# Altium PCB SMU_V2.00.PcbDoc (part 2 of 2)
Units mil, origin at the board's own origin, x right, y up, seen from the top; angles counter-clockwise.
Board outline 8661.42 x 7437.01 mil, 4 copper layers (Component Side, Ground Plane, Power Plane, Solder Side), stack 33.234 mil thick; 223 components, 143 nets, 756 pads, 732 vias.
Unrouted connection lines stored in the file: 6.
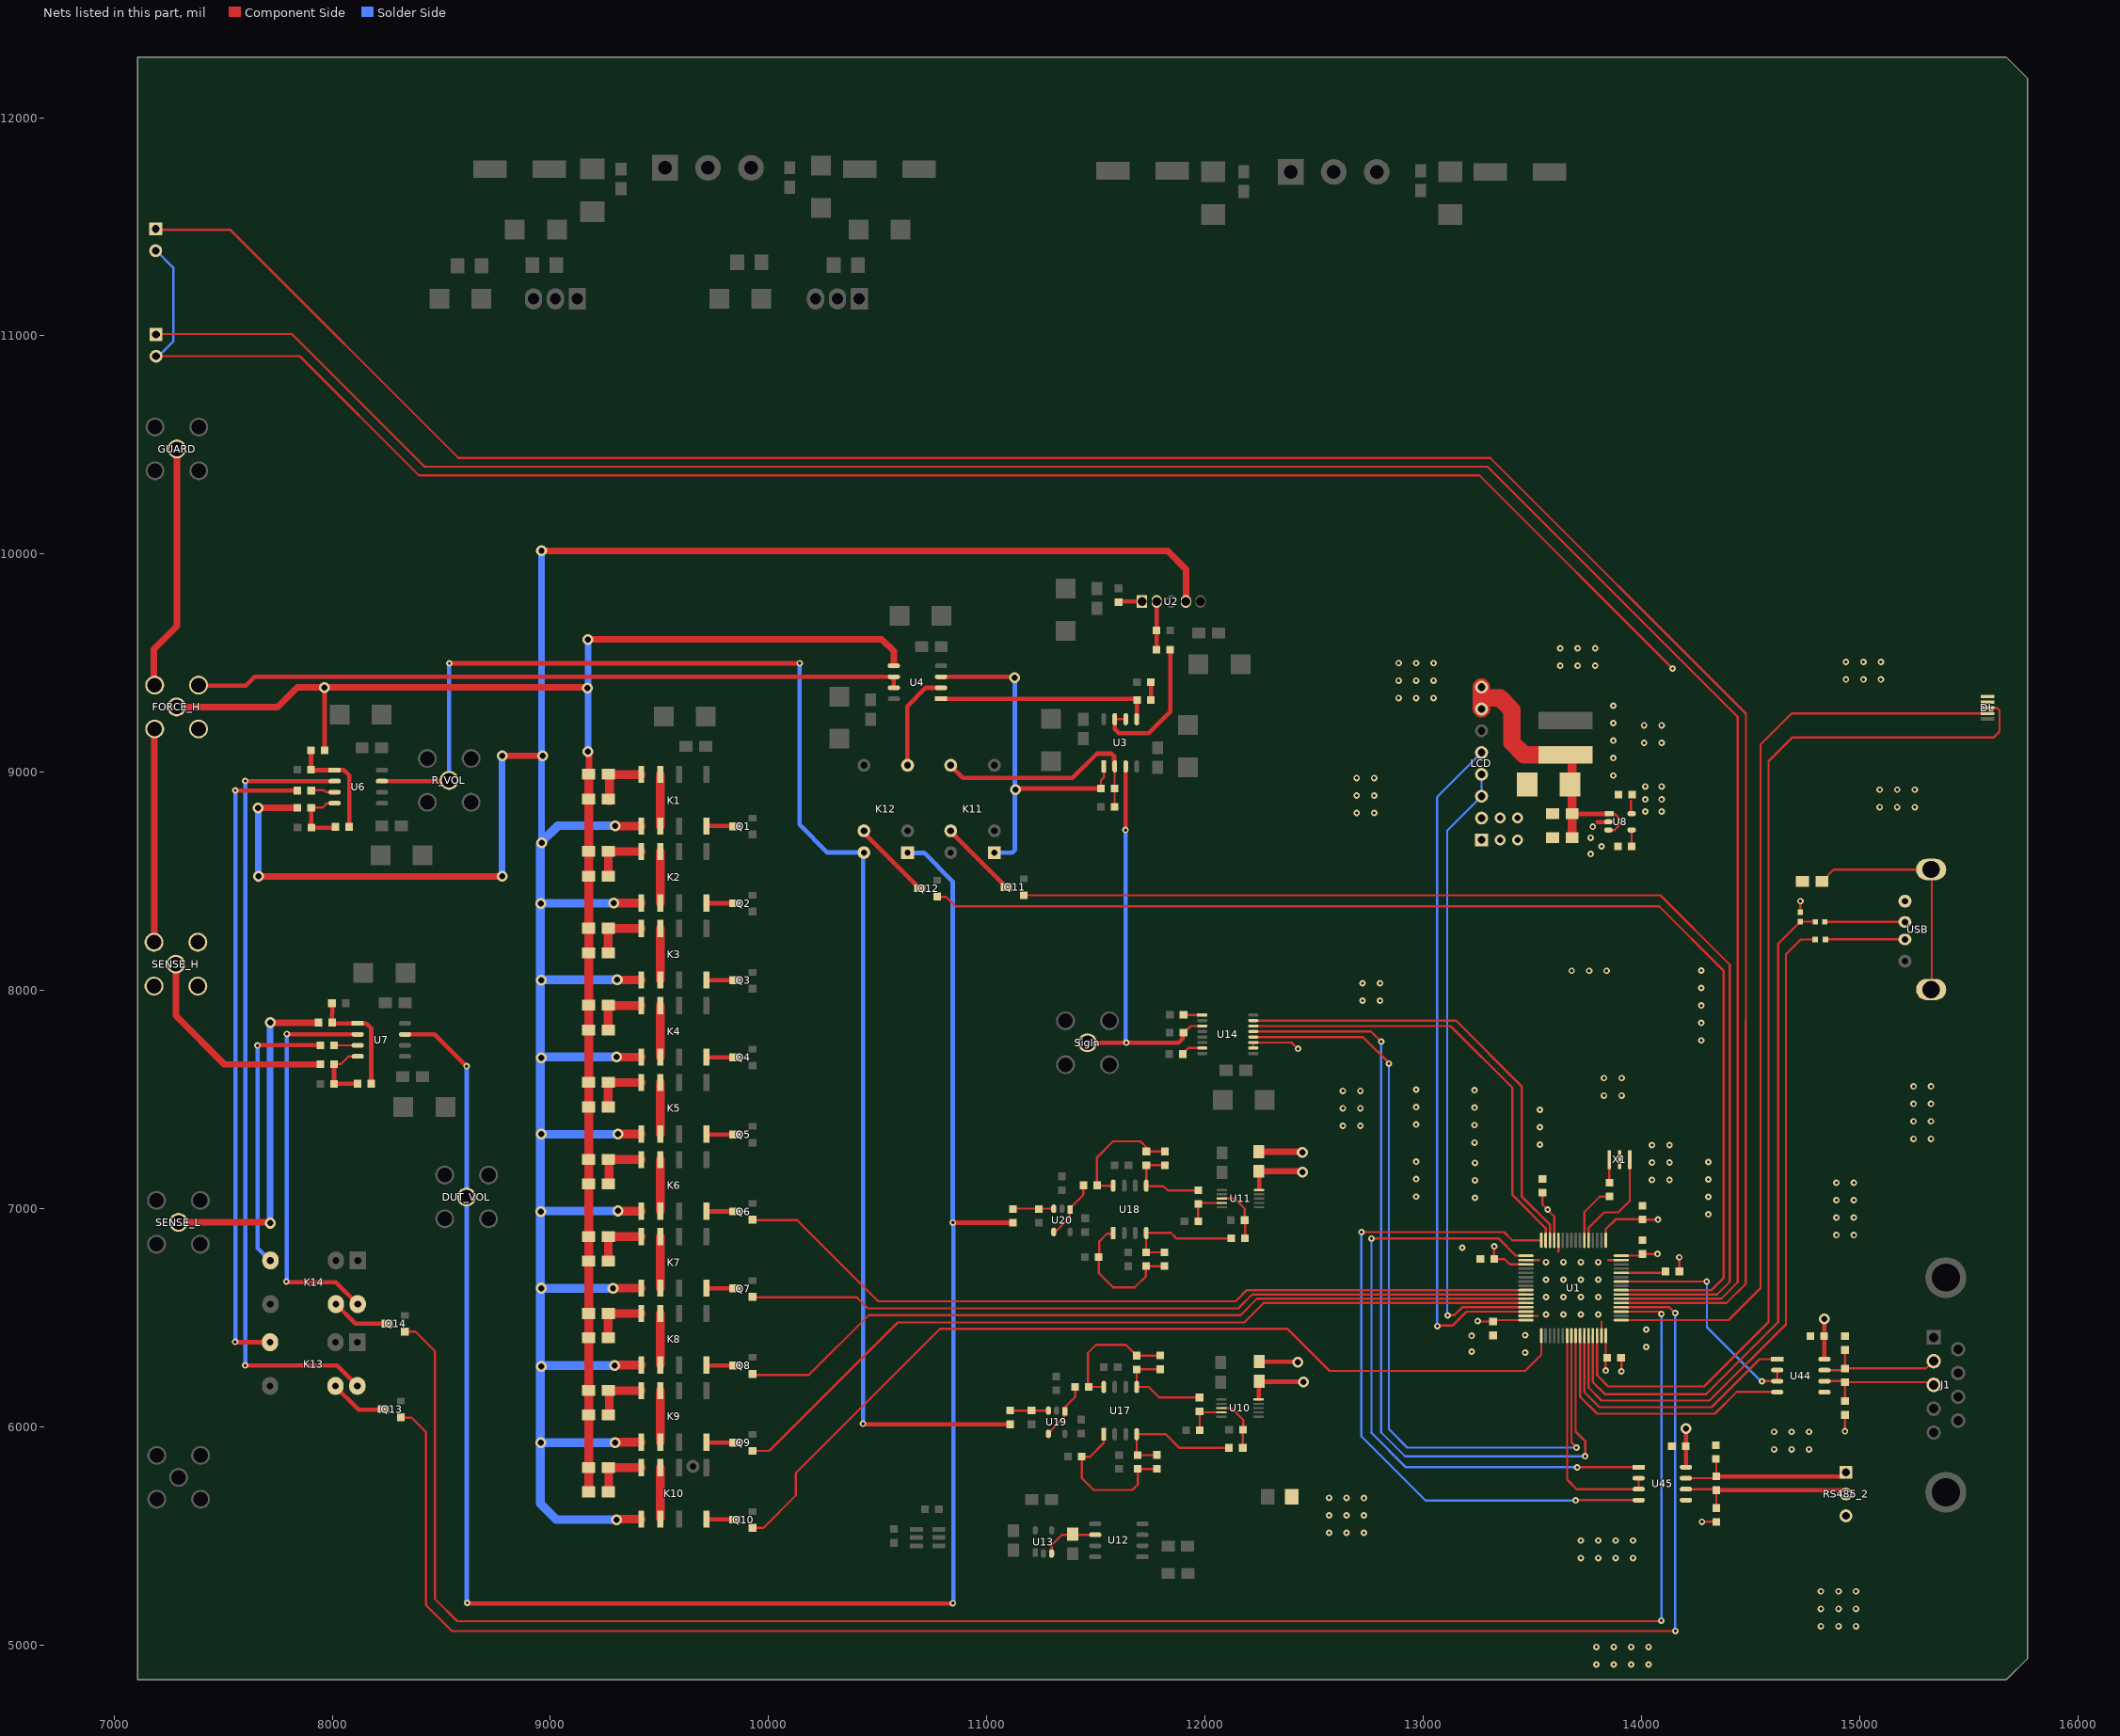
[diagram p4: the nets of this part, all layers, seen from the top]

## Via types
v1: diameter 30/30 (per signal layer), hole 14, Component Side to Solder Side, 595 vias
v2: diameter 50, hole 28, Component Side to Solder Side, 98 vias
v3: diameter 30, hole 14, Component Side to Solder Side, 35 vias
v4: diameter 39.37, hole 29.53, Component Side to Solder Side, 2 vias
v5: diameter 66.93, hole 47.24, Component Side to Solder Side, 2 vias

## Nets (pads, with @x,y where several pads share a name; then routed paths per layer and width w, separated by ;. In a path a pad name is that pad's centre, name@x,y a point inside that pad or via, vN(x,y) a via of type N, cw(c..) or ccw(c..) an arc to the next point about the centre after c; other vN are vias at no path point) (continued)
CTRL6: Q6.1 U1.25 | length 3727.3
  Component Side w10: Q6.1@9917.83,6946.89 10130.76,6946.89 10501.98,6575.67 12140.06,6575.67 12191.29,6626.9 U1.25@13470.11,6626.9
CTRL7: Q7.1 U1.26 | length 3593.2
  Component Side w10: Q7.1@9924.31,6593.69 10404.25,6593.69 10454.72,6543.22 12151.86,6543.22 12211.24,6602.6 12212.32,6602.6 12216.93,6607.22 U1.26@13470.11,6607.22
CTRL8: Q8.1 U1.27 | length 3691.7
  Component Side w10: Q8.1@9922.68,6238.83 10184.86,6238.83 10459.05,6512.43 12162.72,6512.43 12237.82,6587.53 U1.27@13470.11,6587.53
CTRL9: Q9.1 U1.28 | length 3828.3
  Component Side w10: Q9.1@9922.68,5889.82 10002.84,5889.82 10591.34,6478.32 12178.79,6478.32 12268.32,6567.85 U1.28@13470.11,6567.85
CTRL10: Q10.1 U1.33 | length 4271.5
  Component Side w10: Q10.1@9920.57,5537.65 9976.4,5537.65 10124.87,5686.12 10124.87,5788.27 10786.64,6450.03 12376.69,6450.03 12570.4,6256.32 13466.42,6256.32 13540.97,6330.87 U1.33@13540.97,6418.24 ; Q10.1@9922.12,5537.11 Q10.1@9922.12,5551.99
CTRL11: Q11.1 U1.55 | length 5343.6
  Component Side w10: Q11.1@11166.58,8436.12 14086.59,8436.12 14404.05,8118.66 14404.05,6664.84 14346.42,6607.22 U1.55@13907.11,6607.22
CTRL12: Q12.1 U1.56 | length 5650
  Component Side w10: Q12.1@10766.33,8428.85 10813.29,8428.85 10856.41,8385.73 14080.95,8385.74 14375.68,8091.01 14375.68,6681.39 14321.19,6626.9 U1.56@13907.11,6626.9
CTRL13: Q13.1 U1.52 | length 8423.7
  Component Side w10: Q13.1@8316.05,6042.29 8363.72,6042.29 8429.56,5976.45 8429.56,5182.38 8548.04,5063.9 v3@14154.58,5063.9 ; U1.52@13907.11,6548.16 14128.51,6548.16 v3@14154.38,6522.29
  Solder Side w10: v3@14154.38,5064.46 v3(14154.38,6521.19)
  other v3: 14155.22,5065.06
CTRL14: Q14.1 U1.51 | length 8575.1
  Component Side w10: Q14.1@8326.42,6436.35 8381.6,6436.35 8470.69,6347.26 8470.69,5212.23 8573.14,5109.78 v3@14092.23,5109.78 ; U1.51@13907.11,6528.48 14079.18,6528.48 v3@14089.4,6518.25
  Solder Side w10: v3@14091.54,5108.76 v3(14091.54,6517.14)
  other v3: 14090.77,5112.36
D1: K1.8 Q1.3 | length 133.6
  Component Side w20: K1.8@9715.55,8753.74 Q1.3@9849.19,8753.74
D2: K2.8 Q2.3 | length 130.3
  Component Side w20: K2.8@9715.03,8399.71 Q2.3@9845.34,8399.71
D3: K3.8 Q3.3 | length 130.4
  Component Side w20: K3.8@9714.93,8046.63 Q3.3@9845.34,8046.63
D3V3: C1.2 C2.2 C3.2 C4.2 C5.2 C6.2 C22.2 C29.2 C81.2 C85.2 C108.2 LED0.2 LED1.2 R42.1 R102.2 R105.2 U1.1 U1.13 U1.19 U1.32 U1.48 U1.64 U8.5 U10.10 U11.10 U14.10 U14.11 U44.8 U45.8 | length 10898.9
  Component Side w10: LED1.2@7176.54,10907.22 7850.27,10907.22 8397.18,10360.31 13256.88,10360.31 v1(14141.88,9475.31) ; U14.10@12221.05,7736.31 U14.11@12221.05,7758.94 ; U14.11@12226.3,7761.51 12395.95,7761.51 12424.84,7732.62 v1@12426.19,7732.62 ; C81.2@12245.46,6205.52 C81.2@12245.63,6205.52 ; v1@13245.25,6482.49 C6.2@13319.59,6482.49 ; C2.2@13312.76,6768.97 13372.99,6768.97 13396.94,6745.01 U1.19@13470.11,6745.01 ; C6.2@13319.59,6489.11 U1.32@13470.11,6489.11 ; C2.2@13324.77,6770.14 v1@13324.77,6828.08 ; C1.2@13546.28,7074.6 13546.28,7018.74 13600.03,6964.99 U1.13@13600.03,6855.25 ; v1(13835.74,6258.05) C5.2@13835.74,6314.15 ; C5.2@13836.25,6305.29 U1.48@13836.25,6418.24 ; U1.1@13836.25,6855.25 13836.25,6906.38 13881.15,6951.29 C4.2@14009.16,6951.29 ; U1.64@13907.11,6784.38 C3.2@14009.72,6784.38 ; U8.5@13950.9,8809.48 13950.9,8869.84 ; C4.2@14003.81,6950.29 v1@14078.83,6950.29 ; C3.2@14004.91,6792.07 v1@14075.54,6792.07 ; v1(14277.12,5565.07) R105.2@14342.63,5565.07 ; R42.1@14727.91,8358.3 v1(14727.91,8409.28) ; v2(14838.42,6495.31) v2@14838.42,6508.77 ; v1(14932.63,5979.56) R102.2@14932.63,6055.07
  Component Side w20: C81.2@12237.78,6207.05 v2@12452.91,6207.05 ; U10.10@12245.63,6128.67 C81.2@12245.63,6205.52 ; U11.10@12248.04,7089.45 C85.2@12248.04,7167.65 ; U45.8@14203.42,5815.31 v2(14203.42,5991.84) ; U44.8@14838.42,6310.31 v2(14838.42,6495.31)
  Component Side w30: C85.2@12245.91,7171.67 v2@12446.62,7171.67
  Solder Side w10: LED1.2@7192.45,10906.75 7203.88,10906.75 7271.25,10974.11 7271.25,11313 LED0.2@7193.23,11391.03
  other v1: 13248.99,6485.31 14072.89,6792.52 13325.59,6826.87 14075.08,6949.95 13569.87,6996 12426.15,7732.55 14016.88,8820.31 14091.88,8820.31 14016.88,8875.31 14091.88,8875.31 14016.88,8935.31 14091.88,8935.31
  other v2: 12450.69,6206.47 12446.59,7168.16
D4: K4.8 Q4.3 | length 133.8
  Component Side w20: K4.8@9711.55,7693.54 Q4.3@9845.34,7693.54
D5: K5.8 Q5.3 | length 132.6
  Component Side w20: K5.8@9712.77,7340.46 Q5.3@9845.34,7340.46
D5V0: C57.2 C58.2 C59.1 L2.2 LCD.7 LCD.8 U8.1 U8.3 | length 1367.8
  Component Side w10: U8.3@13844.6,8734.68 13876.25,8734.68 13896.88,8755.31 13896.88,8790.31 13877.71,8809.48 U8.1@13844.6,8809.48
  Component Side w22: C58.2@13682.71,8809.48 U8.1@13844.6,8809.48
  Component Side w40: C57.2@13682.34,8700.76 13682.34,8935.31 L2.2@13682.34,9070.07
  Component Side w80: LCD.7@13266.88,9290.31 LCD.8@13266.88,9390.31 ; 13266.88,9340.31 13351.88,9340.31 13406.88,9285.31 13406.88,9135.31 13461.88,9080.31 L2.2@13651.88,9080.31
D6: K6.8 Q6.3 | length 126.8
  Component Side w20: K6.8@9718.57,6987.37 Q6.3@9845.34,6987.37
D7: K7.8 Q7.3 | length 128.9
  Component Side w20: K7.8@9716.44,6634.29 Q7.3@9845.34,6634.29
D8: K8.8 Q8.3 | length 127
  Component Side w20: K8.8@9718.38,6281.21 Q8.3@9845.34,6281.21
D9: K9.8 Q9.3 | length 132
  Component Side w20: K9.8@9713.35,5928.12 Q9.3@9845.34,5928.12
D10: K10.8 Q10.3 | length 128
  Component Side w20: K10.8@9715.55,5576.99 Q10.3@9843.53,5576.99
D11: K11.5 Q11.3 | length 359.8
  Component Side w10: K11.5@10834.46,8728.35 K11.5@10834.46,8732.05
  Component Side w20: K11.5@10834.46,8728.35 Q11.3@11086.28,8476.53
D12: K12.5 Q12.3 | length 371.1
  Component Side w10: K12.5@10436.55,8722.75 K12.5@10436.55,8732.05
  Component Side w20: K12.5@10436.55,8722.75 Q12.3@10692.41,8466.89
D13: K13.5 Q13.3 | length 267.4
  Component Side w10: K13.5@8014.82,6185.08 K13.5@8014.82,6187.86
  Component Side w20: K13.5@8014.82,6185.08 8120.68,6079.23 Q13.3@8235.57,6079.23
D14: K14.5 Q14.3 | length 284.6
  Component Side w20: K14.5@8016.68,6562.69 8106.59,6472.77 Q14.3@8264.05,6472.77
DAC1_FSYNC: U1.41 U14.13 | length 3942.5
  Component Side w10: U14.13@12222.43,7811.9 12760.69,7811.9 ; 12762.48,7809.72 v1(12806.88,7765.31) ; U1.41@13698.45,6418.24 13698.45,5978.74 13741.88,5935.31 v1(13741.88,5865.31)
  Solder Side w10: v1(12806.88,7765.31) 12806.88,5975.31 12916.88,5865.31 v1(13741.88,5865.31)
DAC1_RESET: U1.14 U14.15 | length 2110.4
  Component Side w10: U14.15@12224.6,7862.29 13149.46,7862.29 13450.72,7561.03 13450.72,7056.85 13580.34,6927.22 U1.14@13580.34,6855.25
DAC1_SCLK: U1.40 U14.12 | length 3762.8
  Component Side w10: U14.12@12224.06,7786.7 12723.86,7786.7 12841.88,7668.68 v1(12841.88,7665.31) ; U1.40@13678.77,6418.24 13678.77,5928.43 v1(13701.88,5905.31)
  Solder Side w10: v1(12841.88,7665.31) 12841.88,5990.31 12926.88,5905.31 v1(13701.88,5905.31)
DAC1_SDATA: U1.15 U14.14 | length 2059.5
  Component Side w10: U14.14@12225.14,7837.1 13125.18,7837.1 ; 13127.08,7835.11 13408.8,7553.4 13408.8,7062.49 13560.66,6910.63 U1.15@13560.66,6855.25
DGND: C1.1 C2.1 C3.1 C4.1 C5.1 C6.1 C22.1 C23.1 C29.1 C57.1 C58.1 C59.2 C81.1 C85.1 C108.1 DL.5 L1.2 L3.2 LCD.1 LCD.2 R2.2 R101.2 R104.2 RS485_2.3 U1.12 U1.18 U1.31 U1.47 U1.63 U8.2 U44.5 U45.5 USB.4 X1.2 | length 843.6
  Component Side w10: U1.31@13470.11,6508.79 13525.37,6508.79 ; U1.18@13470.11,6764.7 13531.27,6764.7 ; 13619.71,6802.48 U1.12@13619.71,6855.25 ; U1.47@13816.56,6418.24 13816.56,6481.79 ; 13847.49,6764.7 U1.63@13907.11,6764.7 ; v1(13907.96,6253.87) C5.1@13907.96,6317.13 ; R2.2@14173.57,6712.43 v1@14173.57,6775.64
  Component Side w20: C81.1@12249.04,6299.06 v2@12422.09,6299.06 ; 13798.66,8772.08 U8.2@13844.6,8772.08
  Component Side w30: C85.1@12245.91,7261.67 v2@12451.64,7261.67
  other v1: 13792.56,4911.52 13872.56,4911.52 13952.56,4911.52 14032.56,4911.52 13792.56,4991.52 13872.56,4991.52 13952.56,4991.52 14032.56,4991.52 14822.53,5086.38 14902.53,5086.38 14982.53,5086.38 14822.53,5166.38 14902.53,5166.38 14982.53,5166.38 14822.53,5246.38 14902.53,5246.38 14982.53,5246.38 13721.63,5399.14 13801.63,5399.14 13881.63,5399.14 13961.63,5399.14 13721.63,5479.14 13801.63,5479.14 13881.63,5479.14 13961.63,5479.14 12568.37,5515.09 12648.37,5515.09 12728.37,5515.09 12568.37,5595.09 12648.37,5595.09 12728.37,5595.09 12728.25,5673.54 12568.37,5675.09 12648.37,5675.09 14607.34,5897.3 14687.34,5897.3 14767.34,5897.3 14607.34,5977.3 14687.34,5977.3 14767.34,5977.3 13466.88,6340.31 13221.75,6344.34 14021.33,6366.39 13220.96,6417.42 13466.88,6420.31 14021.33,6446.39 13561.88,6515.31 13641.88,6515.31 13721.88,6515.31 13801.88,6515.31 13561.88,6595.31 13641.88,6595.31 13721.88,6595.31 13801.88,6595.31 13561.88,6675.31 13641.88,6675.31 13721.88,6675.31 13801.88,6675.31 13561.88,6755.31 13641.88,6755.31 13721.88,6755.31 13801.88,6755.31 14173.16,6777.15 13178.69,6821.71 14893.33,6879.01 14973.33,6879.01 14893.33,6959.01 14973.33,6959.01 14306.08,6973.73 14893.33,7039.01 14973.33,7039.01 13236.88,7050.31 14306.08,7053.73 12966.88,7055.31 14893.33,7119.01 14973.33,7119.01 13236.88,7130.31 14048.35,7131.47 14128.35,7131.47 14306.08,7133.73 12966.88,7135.31 13236.88,7210.31 14048.35,7211.47 14128.35,7211.47 14306.08,7213.73 12966.88,7215.31 14048.35,7291.47 14128.35,7291.47 13534.13,7293.67 13234.52,7303.01 15246.88,7320.31 15326.88,7320.31 13534.13,7373.67 12631.88,7380.31 12711.88,7380.31 13234.52,7383.01 12966.88,7385.31 15246.88,7400.31 15326.88,7400.31 13534.13,7453.67 12631.88,7460.31 12711.88,7460.31 13234.52,7463.01 12966.88,7465.31 15246.88,7480.31 15326.88,7480.31 13828.57,7518.66 13908.57,7518.66 12631.88,7540.31 12711.88,7540.31 13234.52,7543.01 12966.88,7545.31 15246.88,7560.31 15326.88,7560.31 13828.57,7598.66 13908.57,7598.66 14273.54,7771.1 14273.54,7851.1 14273.54,7931.1 12721.88,7953.43 12801.88,7953.43 14273.54,8011.1 12721.88,8033.43 12801.88,8033.43 13679.84,8090.23 13759.84,8090.23 13839.84,8090.23 14273.54,8091.1 13766.88,8625.31 13816.88,8660.31 13766.88,8700.31 13776.88,8750.31 12694.62,8813.79 12774.62,8813.79 15091.88,8840.31 15171.88,8840.31 15251.88,8840.31 12694.62,8893.79 12774.62,8893.79 15091.88,8920.31 15171.88,8920.31 15251.88,8920.31 12694.62,8973.79 12774.62,8973.79 13870.46,8985.13 13870.46,9065.13 14011.88,9135.31 14091.88,9135.31 13870.46,9145.13 14011.88,9215.31 14091.88,9215.31 13870.46,9225.13 13870.46,9305.13 12886.88,9340.31 12966.88,9340.31 13046.88,9340.31 12886.88,9420.31 12966.88,9420.31 13046.88,9420.31 14936.88,9425.31 15016.88,9425.31 15096.88,9425.31 13627.78,9488.72 13707.78,9488.72 13787.78,9488.72 12886.88,9500.31 12966.88,9500.31 13046.88,9500.31 14936.88,9505.31 15016.88,9505.31 15096.88,9505.31 13627.78,9568.72 13707.78,9568.72 13787.78,9568.72
  other v2: 12425.75,6296.93 12445.7,7258.73 13351.88,8690.31 13431.88,8690.31 13351.88,8790.31 13431.88,8790.31
DUT_VOLTAGE: DUT_VOL.1 K12.1 R51.2 U7.7 | length 8897.1
  Component Side w20: U7.7@8333.23,7798.88 8468.01,7798.88 v3@8613.08,7653.82 ; v3@8614.43,5190.9 v3@10847.87,5190.9 ; v3@10841.24,6935.57 R51.2@11119.82,6935.57
  Solder Side w20: v3@8616.34,5192.67 v3@8616.34,7656.93 ; K12.1@10633.99,8630.67 10712.84,8630.67 10843.28,8500.23 v3@10843.28,6935.17 ; v3@10845.98,5191.13 v3@10845.98,6943.61
  other v3: 10844.16,5191.95 8618.51,5193.22 10844.41,6936.49 8615.4,7652.69
FB_R_T1: C70.1 C71.1 C72.1 C73.1 C74.1 C75.1 C76.1 C77.1 C78.1 C79.1 FORCE_H.1 R19.2 R31.1 R32.1 R33.1 R34.1 R35.1 R36.1 R37.1 R38.1 R39.1 R40.1 U4.5 | length 7622.6
  Component Side w10: v2(7963.23,9388.71) v2@7965.15,9388.71
  Component Side w20: R19.2@7965.15,9100.94 v2@7965.15,9388.71
  Component Side w30: FORCE_H.1@7284.41,9298.47 7748.92,9298.47 7839.16,9388.71 v2(7963.23,9388.71) ; v2@7965.15,9388.71 v2@9170.85,9388.71 ; v2@9165.48,9609.56 10518.48,9609.56 10573.43,9554.61 U4.5@10573.43,9491.17 ; R31.1@9171.24,8985.77 9176.58,8991.11 v2@9176.58,9099.16
  Component Side w40: C79.1@9175.42,5705.38 R40.1@9175.42,5813.12 C78.1@9175.42,6055.22 R39.1@9175.42,6166.28 C77.1@9175.42,6407.94 R38.1@9175.42,6519.44 C76.1@9175.42,6760.67 R37.1@9175.42,6872.6 C75.1@9175.42,7113.4 R36.1@9175.42,7225.76 C74.1@9175.42,7466.13 R35.1@9175.42,7578.92 C73.1@9175.42,7818.86 R34.1@9175.42,7932.09 C72.1@9175.42,8171.58 R33.1@9175.42,8285.25 C71.1@9175.42,8524.31 R32.1@9175.42,8638.41 C70.1@9175.42,8877.04 R31.1@9175.42,8991.57
  Solder Side w30: v2(9171.77,9095) v2@9171.77,9610.04
  other v2: 9169.88,9386.28 9171.77,9608.65
FB_R_T2: K1.5 K2.5 K3.5 K4.5 K5.5 K6.5 K7.5 K8.5 K9.5 K10.5 R21.2 U2.4 | length 14501
  Component Side w30: v2@7654.09,8837.22 R21.2@7840.73,8837.22 ; v2(7662.06,8523.46) v2@8776.36,8523.46 ; v2(8779.53,9075.6) v2@8961.35,9075.6 ; v2@8955.66,10013.74 11828.42,10013.74 11911.99,9930.18 U2.4@11911.99,9782.7
  Component Side w40: v2@9287.6,6635.91 K7.5@9416.34,6635.91 ; v2@9288.99,8400.76 K2.5@9416.34,8400.76 ; v2@9289.28,6282.93 K8.5@9416.34,6282.93 ; v2@9296.82,5929.96 K9.5@9416.34,5929.96 ; v2@9297.25,7694.82 K4.5@9416.34,7694.82 ; v2@9298.95,8753.74 K1.5@9416.34,8753.74 ; v2@9304.27,5576.99 K10.5@9416.34,5576.99 ; v2@9307.92,8047.79 K3.5@9416.34,8047.79 ; v2@9309.83,6988.88 K6.5@9416.34,6988.88 ; v2@9314.01,7341.85 K5.5@9416.34,7341.85
  Solder Side w10: v2@8952.92,6989.61 v2@8953.9,6989.61 ; v2(8959.34,8676.88) v2@8959.34,8680.45
  Solder Side w30: v2@7660.42,8511.83 v2(7660.42,8836.35) ; v2(8778.29,8524.51) v2@8778.29,9063.78 ; v2@8959.34,8680.45 v2@8959.34,10012.66
  Solder Side w40: v2@8956.15,6281.23 v2(9293.52,6281.23) ; v2@8957.46,6634.94 v2(9286.79,6634.94) ; v2@8960.46,7695.1 v2(9303.13,7695.1) ; v2@8960.49,8399.92 v2(9289.6,8399.92) ; v2@8962.72,8049.77 v2(9306.02,8049.77) ; v2@8963.99,7341.39 v2(9308.9,7341.39) ; v2(9296.41,5927.52) v2@8953.9,5927.52 ; v2@9300.6,8755.61 9034.5,8755.61 8959.34,8680.45 8953.9,8675.01 v2@8953.9,6989.61 ; v2(9303.13,5574.77) 9027.3,5574.77 8953.9,5648.16 v2@8953.9,5927.52 ; v2(9308.9,6989.61) v2@8953.9,6989.61 ; v2@8953.9,5927.52 v2@8953.9,6989.61
  other v2: 8956.45,5927.42 8957.77,6277.33 8958.42,6635.77 8956.45,6986.34 8957.77,7341.49 8957.11,7692.06 8957.11,8047.88 8956.45,8399.1 9296.1,8754.49 8963.98,9074.94 8959.06,10015.26
GUARD: FORCE_H.2 GUARD.1 SENSE_H.2 U4.6 U4.7 | length 5394.3
  Component Side w10: SENSE_H.2@7175.5,8220.98 SENSE_H.2@7184.03,8220.98 ; SENSE_H.2@7383.96,8011.56 SENSE_H.2@7383.96,8020.19 ; U4.6@10573.43,9437.78 U4.6@10573.43,9441.73
  Component Side w20: FORCE_H.2@7391,9397.04 7604.57,9397.04 7645.76,9438.23 10573.43,9438.23 U4.7@10573.43,9387.39
  Component Side w30: FORCE_H.2@7177.03,9209.76 7184.03,9202.76 SENSE_H.2@7184.03,8220.98 ; FORCE_H.2@7182.05,9394.91 7182.05,9563.93 7288.07,9669.95 GUARD.1@7288.07,10482.17
LED0: LED0.1 U1.53 | length 11453.1
  Component Side w10: LED0.1@7185.6,11486.63 7531.88,11486.63 8578.2,10440.31 13306.88,10440.31 14478.49,9268.71 14478.49,7842.78 ; U1.53@13907.11,6567.85 14389.55,6567.85 14478.3,6656.6 14478.3,7864.21
LED1: LED1.1 U1.54 | length 11129
  Component Side w10: LED1.1@7192.3,11008.95 7813.24,11008.95 ; 7815.16,11008.5 8423.36,10400.31 13293.67,10400.31 14440.94,9253.04 14440.94,6662.88 14365.59,6587.53 U1.54@13907.11,6587.53
NetC7_1: C7.1 R46.2 U10.4 | length 184.1
  Component Side w10: C7.1@11975.15,5985.45 11975.15,6066.65 U10.4@12078.05,6066.65
NetC8_1: C8.1 R47.2 U11.4 | length 201.2
  Component Side w10: R47.2@11962.48,7026.48 R47.2@11967.48,7026.48 ; C8.1@11968.3,6941.34 R47.2@11968.3,7030.77 ; R47.2@11970.04,7026.48 U11.4@12076.78,7026.48
NetC20_2: C20.2 R10.2 U2.2 | length 219.2
  Component Side w20: R10.2@11777.83,9568.07 U2.2@11777.83,9787.27
NetC21_1: C21.1 R16.2 | length 86.5
  Component Side w20: R16.2@11751.7,9325.35 C21.1@11751.7,9411.88
NetC23_2: C23.2 U8.4 | length 72.4
  Component Side w10: C23.2@13954.72,8663.27 U8.4@13954.72,8735.63
NetC30_1: C30.1 C31.2 R19.1 U6.1 | length 512.4
  Component Side w10: R19.1@7902.5,9101.28 R19.1@7905.61,9104.39
  Component Side w20: C31.2@7902.5,9011.2 R19.1@7902.5,9101.28 ; C31.2@7903.03,9009.61 U6.1@8020.41,9009.61 ; U6.1@8019.88,9011.22 8053.04,9011.22 8077.97,8986.29 C30.1@8077.97,8754.22
NetC30_2: C30.2 C32.1 R21.1 U6.4 | length 322.1
  Component Side w10: R21.1@7900.64,8838.15 7955.88,8838.15 7976.25,8858.53 U6.4@8011,8858.53 ; C32.1@7900.93,8748.07 C32.1@7903.72,8748.07
  Component Side w20: C32.1@7903.72,8749.15 R21.1@7903.72,8837.22 ; C32.1@7904.25,8746.51 C30.2@8016.66,8746.51
NetC33_2: C33.2 C34.1 R12.2 U7.1 | length 533
  Component Side w20: C33.2@7999.92,7942.89 8000.36,7942.42 7998.42,7848.98 U7.1@8108.09,7848.98 ; U7.1@8116.7,7849.28 8156.27,7849.28 8178.58,7826.97 C34.1@8178.58,7568.9
NetC34_2: C34.2 C35.1 R14.2 U7.4 | length 318.2
  Component Side w10: R14.2@8007.98,7662.74 8039.6,7662.74 8074.15,7697.29 U7.4@8117.52,7697.29
  Component Side w20: C35.1@8007.98,7574.69 R14.2@8007.98,7662.74 ; C35.1@8008.35,7572.23 C34.2@8114.65,7572.23
NetC49_1: C49.1 U14.1 | length 87.2
  Component Side w10: C49.1@11899.97,7887.49 U14.1@11987.2,7887.49
NetC70_2: C70.2 K1.4 R31.2 | length 267.6
  Component Side w40: C70.2@9270.78,8867.93 9270.78,8989.96 K1.4@9416.34,8989.96
NetC71_2: C71.2 K2.4 R32.2 | length 252.5
  Component Side w40: C71.2@9265.42,8526.63 R32.2@9265.42,8638.41 ; R32.2@9275.65,8636.98 K2.4@9416.34,8636.98
NetC72_2: C72.2 K3.4 R33.2 | length 255.1
  Component Side w10: C72.2@9263.99,8196.39 C72.2@9274.69,8185.68
  Component Side w40: C72.2@9263.99,8196.39 9263.99,8284.01 K3.4@9416.34,8284.01
NetC73_2: C73.2 K4.4 R34.2 | length 262.3
  Component Side w10: C73.2@9264.32,7822.44 C73.2@9265.53,7821.24
  Component Side w40: C73.2@9264.32,7822.44 9264.32,7931.04 K4.4@9416.34,7931.04
NetC74_2: C74.2 K5.4 R35.2 | length 262.6
  Component Side w40: C74.2@9263.58,7468.25 9263.58,7578.07 K5.4@9416.34,7578.07
NetC75_2: C75.2 K6.4 R36.2 | length 264.2
  Component Side w10: R36.2@9268.3,7224.97 R36.2@9268.43,7225.1
  Component Side w40: C75.2@9268.3,7108.84 R36.2@9268.3,7224.97 ; R36.2@9268.43,7225.1 K6.4@9416.34,7225.1
NetC76_2: C76.2 K7.4 R37.2 | length 260.5
  Component Side w40: C76.2@9265.3,6762.64 9265.3,6872.13 K7.4@9416.34,6872.13
NetC77_2: C77.2 K8.4 R38.2 | length 260
  Component Side w40: C77.2@9264.02,6411.52 9264.02,6519.15 K8.4@9416.34,6519.15
NetC78_2: C78.2 K9.4 R39.2 | length 253.3
  Component Side w40: C78.2@9269.23,6060.03 9269.23,6166.18 K9.4@9416.34,6166.18
NetC79_2: C79.2 K10.4 R40.2 | length 257.4
  Component Side w40: C79.2@9267.22,5704.95 9267.22,5813.21 K10.4@9416.34,5813.21
NetC80_1: C80.1 R30.2 U10.3 | length 257.4
  Component Side w10: U10.3@12074.37,6086.22 12120.93,6086.22 12174.55,6032.6 12174.55,5982.89 C80.1@12174.83,5982.61 ; R30.2@12172.64,5904.18 C80.1@12172.64,5989.13
NetC84_1: C84.1 R29.2 U11.3 | length 265.5
  Component Side w10: U11.3@12076.78,7046.17 12136.01,7046.17 12181.69,7000.48 C84.1@12181.69,6943.88 ; R29.2@12182.89,6865.24 C84.1@12182.89,6950.33
NetC90_2: C90.2 U12.6 U13.3 | length 262.9
  Component Side w10: U13.3@11296.75,5419.78 11296.75,5457.23 11344.13,5504.61 11499.93,5504.61 U12.6@11501.83,5506.51
NetC122_1: C122.1 R53.1 R54.2 U17.8 | length 607.4
  Component Side w10: R53.1@11463.37,6177.59 11463.37,6339.46 11499.68,6375.77 11636.94,6375.77 R54.2@11686.37,6326.34 C122.1@11805.71,6326.34 ; R53.1@11468.77,6180.73 11468.77,6182.81 U17.8@11534.36,6182.81
NetC122_2: C122.2 R46.1 R54.1 U17.5 | length 492.2
  Component Side w10: R54.1@11686.37,6263.35 R54.1@11686.79,6263.35 ; C122.2@11790.03,6263.35 R54.1@11686.79,6263.35 ; R46.1@11974.74,6134.21 11790.46,6134.21 11741.74,6182.93 U17.5@11686.79,6182.93 R54.1@11686.79,6263.35
NetC123_1: C123.1 R30.1 R56.2 U17.4 | length 644.2
  Component Side w10: R56.2@11687.72,5871.76 11686.79,5872.69 U17.4@11686.79,5966.4 11819.79,5966.4 11882.87,5903.32 R30.1@12112.1,5903.32 ; R56.2@11690.74,5870.48 C123.1@11788.5,5870.48
NetC123_2: C123.2 R55.1 R56.1 U17.1 | length 720.8
  Component Side w10: R55.1@11435.08,5863.29 11435.08,5765.37 11489.43,5711.02 11666.85,5711.02 11692.29,5736.46 R56.1@11692.29,5807.98 ; R55.1@11435.56,5863.38 11472.75,5863.38 11535.61,5926.23 U17.1@11535.61,5966.4 ; R56.1@11690.74,5807.49 C123.2@11785.58,5807.49
NetC124_1: C124.1 R57.1 R58.2 U18.8 | length 563.5
  Component Side w10: R57.1@11504.96,7107.88 11504.96,7235.88 11577.95,7308.87 11703.72,7308.87 11730.77,7281.82 C124.1@11730.77,7262.29 ; R57.1@11510.97,7105.34 U18.8@11579.13,7105.34 ; C124.1@11735.09,7262.31 R58.2@11815.64,7262.31
NetC124_2: C124.2 R47.1 R58.1 U18.5 | length 422
  Component Side w10: U18.5@11726.01,7102.54 11809.85,7102.54 11828.78,7083.6 R47.1@11958.29,7083.6 ; U18.5@11730.31,7105.34 C124.2@11730.31,7197.49 ; C124.2@11730.77,7199.3 R58.1@11820.46,7199.3
NetC125_1: C125.1 R29.1 R60.2 U18.4 | length 596.9
  Component Side w10: U18.4@11729.76,6899.75 R60.2@11729.76,6799.48 R60.2@11729.87,6799.48 ; R60.2@11729.87,6791.29 R60.2@11729.87,6799.48 ; U18.4@11730.26,6888.89 11842.71,6888.89 11867.68,6863.92 R29.1@12122.35,6863.92 ; C125.1@11815.73,6799.48 R60.2@11729.87,6799.48
NetC125_2: C125.2 R59.1 R60.1 U18.1 | length 633.7
  Component Side w10: R59.1@11512.72,6778.01 11512.72,6704.62 11578.41,6638.93 11676.76,6638.93 11729.09,6691.27 R60.1@11729.09,6739.59 ; R59.1@11514.82,6778.53 11514.82,6849.92 11549.52,6884.61 11574.94,6884.61 U18.1@11579.13,6888.8 ; R60.1@11729.76,6736.49 C125.2@11824.74,6736.49
NetJ1_2: J1.2 R100.1 R101.1 U44.7 | length 598
  Component Side w10: U44.7@14838.42,6259.91 R100.1@14929.48,6259.91 ; R101.1@14932.63,6352.55 R100.1@14932.63,6268.06 15303.67,6268.06 J1.2@15340.01,6304.4
NetJ1_3: J1.3 R100.2 R102.1 U44.6 | length 577.3
  Component Side w10: U44.6@14838.42,6209.52 R100.2@14933.18,6209.52 ; R102.1@14932.63,6118.06 R100.2@14932.63,6205.07 ; R100.2@14933.18,6205.07 J1.3@15328.72,6205.07
NetK1_3: K1.3 K1.6 | length 239.2
  Component Side w10: K1.3@9502.95,8989.96 K1.3@9502.95,8992.97
  Component Side w40: K1.6@9502.95,8753.74 K1.3@9502.95,8989.96
NetK2_3: K2.3 K2.6 | length 236.2
  Component Side w40: K2.6@9502.95,8400.76 K2.3@9502.95,8636.98
NetK3_3: K3.3 K3.6 | length 243.5
  Component Side w10: K3.6@9502.95,8040.53 K3.6@9502.95,8047.79
  Component Side w40: K3.6@9502.95,8047.79 K3.3@9502.95,8284.01
NetK4_3: K4.3 K4.6 | length 238.4
  Component Side w10: K4.6@9502.95,7692.6 K4.6@9502.95,7694.82
  Component Side w40: K4.6@9502.95,7694.82 K4.3@9502.95,7931.04
NetK5_3: K5.3 K5.6 | length 238.2
  Component Side w10: K5.6@9502.95,7339.91 K5.6@9502.95,7341.85
  Component Side w40: K5.6@9502.95,7341.85 K5.3@9502.95,7578.07
NetK6_3: K6.3 K6.6 | length 238.7
  Component Side w10: K6.6@9502.95,6986.41 K6.6@9502.95,6988.88
  Component Side w40: K6.6@9502.95,6988.88 K6.3@9502.95,7225.1
NetK7_3: K7.3 K7.6 | length 243.2
  Component Side w10: K7.6@9502.95,6628.95 K7.6@9502.95,6635.91
  Component Side w40: K7.6@9502.95,6635.91 K7.3@9502.95,6872.13
NetK8_3: K8.3 K8.6 | length 237.3
  Component Side w10: K8.6@9502.95,6281.81 K8.6@9502.95,6282.93
  Component Side w40: K8.6@9502.95,6282.93 K8.3@9502.95,6519.15
NetK9_3: K9.3 K9.6 | length 240.2
  Component Side w10: K9.6@9502.95,5925.94 K9.6@9502.95,5929.96
  Component Side w40: K9.6@9502.95,5929.96 K9.3@9502.95,6166.18
NetK10_3: K10.3 K10.6 | length 232
  Component Side w40: K10.6@9502.95,5581.19 K10.3@9502.95,5813.21
NetK11_1: K11.1 R18.1 U3.1 U4.3 | length 1736.4
  Component Side w10: R18.1@11522.85,8925.56 11522.85,8963.19 11536.05,8976.39 U3.1@11536.05,9031.3
  Component Side w20: U4.3@10789.97,9437.78 v2@11129.97,9437.78 ; v2@11130.36,8925.56 R18.1@11522.85,8925.56
  Solder Side w20: K11.1@11034.59,8632.21 11116.43,8632.21 11128.37,8644.15 v2@11128.37,9438.15
  other v2: 11131.89,8920.77 11126.63,9432.66
NetK11_4: K11.4 R17.1 R18.2 U3.2 | length 1071.8
  Component Side w10: R17.1@11584.86,8841.62 U3.2@11584.86,9030.75
  Component Side w20: K11.4@10832.28,9031.55 10889.98,8973.86 11392.39,8973.86 11503.71,9085.18 11571.91,9085.18 11582.78,9074.3 U3.2@11582.78,9016.61
NetK12_3: K12.3 U4.2 | length 463.6
  Component Side w20: K12.3@10634.78,9029.12 10634.78,9302.37 10719.8,9387.39 U4.2@10789.97,9387.39
NetK13_3: K13.3 R44.1 | length 2978.4
  Component Side w20: v3@7551.15,6387.86 K13.3@7714.82,6387.86 ; v3@7554.04,8916.16 R44.1@7840.57,8916.16
  Solder Side w20: v3@7555.85,6388.71 v3(7555.85,8916.88)
  other v3: 7554.86,6389.41
NetK14_3: K14.3 R45.1 | length 1298.9
  Component Side w20: v3@7656.08,7749.31 R45.1@7945.26,7749.31
  Solder Side w20: v3(7657.53,7747.78) 7657.53,6819.38 K14.3@7715,6761.91
NetL1_1: L1.1 USB.5 USB.6 | length 1064.7
  Component Side w10: L1.1@14826.88,8500.31 14880.97,8554.39 USB.5@15319.17,8554.39 ; USB.6@15330.03,8004.39 USB.5@15330.03,8554.39
NetR1_1: R1.1 X1.3 | length 103.8
  Component Side w10: R1.1@13851.87,7121.39 X1.3@13851.87,7225.16
NetR1_2: R1.2 U1.6 | length 275.5
  Component Side w10: U1.6@13737.82,6855.25 13737.82,6984.11 13809.19,7055.48 R1.2@13854.91,7055.48
NetR2_1: R2.1 U1.60 | length 208.7
  Component Side w10: U1.60@13907.11,6705.64 14113.85,6705.64 R2.1@14115.22,6707.02
NetR10_1: R10.1 U3.6 U3.7 | length 683.2
  Component Side w10: U3.7@11586.12,9243.47 U3.6@11636.52,9243.47
  Component Side w20: U3.7@11586.12,9243.47 11586.12,9197.63 11604.62,9179.13 11741.7,9179.13 11840.84,9278.27 R10.1@11840.84,9561.81
NetR16_1: R16.1 U3.5 U4.1 | length 978.4
  Component Side w20: U4.1@10789.97,9336.99 R16.1@11682.46,9336.99 ; U3.5@11686.91,9243.47 R16.1@11686.91,9329.35
NetR27_2: R27.2 U2.1 | length 106.2
  Component Side w20: R27.2@11604.98,9782.7 U2.1@11711.2,9782.7
NetR41_1: R41.1 USB.3 | length 368.9
  Component Side w10: R41.1@14839.88,8314.28 USB.3@15208.81,8314.28
NetR43_1: R43.1 USB.2 | length 362.1
  Component Side w10: R43.1@14844.26,8234.28 USB.2@15206.37,8234.28
NetR49_1: R49.1 R50.2 U19.3 | length 175.2
  Component Side w10: R49.1@11106.56,6074.79 U19.3@11281.75,6074.79
NetR51_1: R51.1 R52.2 U20.3 | length 184
  Component Side w10: R51.1@11123.35,7000.27 U20.3@11307.33,7000.27
NetR53_2: R53.2 U19.1 U19.4 | length 269.1
  Component Side w10: U19.4@11279.78,5967.27 11279.78,5969.84 11356.78,6046.84 U19.1@11356.78,6070.72 11356.78,6089.44 11405.1,6137.76 R53.2@11405.1,6184.44
NetR57_2: R57.2 U20.1 U20.4 | length 275.2
  Component Side w10: U20.4@11306.66,6893.43 11313.28,6893.43 11380.19,6960.35 11380.19,6998.29 11383.42,7001.52 11383.42,7004.75 11441.54,7062.87 R57.2@11441.54,7108.89
NetR103_1: R103.1 R104.1 RS485_2.1 U45.7 | length 790.1
  Component Side w10: U45.7@14203.42,5764.91 R103.1@14334.48,5764.91 ; R103.1@14342.63,5773.06 R104.1@14342.63,5851.06
  Component Side w20: R103.1@14342.63,5773.06 RS485_2.1@14923.63,5773.06
NetR103_2: R103.2 R105.1 RS485_2.2 U45.6 | length 811.4
  Component Side w10: U45.6@14203.42,5714.52 R103.2@14338.18,5714.52 ; R105.1@14342.63,5628.06 R103.2@14342.63,5710.07
  Component Side w20: R103.2@14342.63,5710.07 RS485_2.2@14937.29,5710.07
NetU1_5: U1.5 X1.1 | length 488.3
  Component Side w10: U1.5@13757.51,6855.25 13757.51,6912.35 13828.5,6983.34 13893.52,6983.34 13946.36,7036.17 X1.1@13946.36,7227.19
NULL: C47.1 U14.7 | length 101.8
  Component Side w10: C47.1@11896.7,7709.05 11923.95,7736.31 U14.7@11987.2,7736.31
R_VOLTAGE: K12.6 R49.2 R_VOL.1 U6.7 | length 6857.9
  Component Side w20: U6.7@8227.53,8959.32 R_VOL.1@8561.53,8959.32 ; v3(8536.47,9499.16) v3@10138.1,9499.16 ; v3@10427.3,6011.79 R49.2@11106.56,6011.79
  Solder Side w20: R_VOL.1@8535.82,8963.27 v3@8535.82,9498.18 ; v3(10141.8,9500.2) 10141.8,8760.21 10269.76,8632.25 K12.6@10439.07,8632.25 ; v3(10432.51,6014.4) K12.6@10432.51,8632.18
RG1+: K13.6 U6.2 | length 3652.1
  Component Side w20: v3@7596.22,6281.31 8021.37,6281.31 K13.6@8114.82,6187.86 ; v3@7596.41,8959.32 U6.2@8011,8959.32
  Solder Side w20: v3@7601.38,6279.82 v3(7601.38,8960.04)
  other v3: 7601.19,6281.59
RG1-: R44.2 U6.3 | length 111.3
  Component Side w10: R44.2@7903.59,8918.28 7960.93,8918.28 7970.29,8908.92 U6.3@8011,8908.92
RG2+: K14.6 U7.2 | length 1835.9
  Component Side w20: v3@7786.39,7798.88 U7.2@8116.7,7798.88 ; v3@7787.9,6662.95 8016.41,6662.95 K14.6@8116.68,6562.69
  Solder Side w20: v3@7791.8,6665.94 v3(7791.8,7801.25)
  other v3: 7789.41,6665.98
RG2-: R45.2 U7.3 | length 112.8
  Component Side w10: R45.2@8003.85,7748.49 U7.3@8116.7,7748.49
RS485_RE: U1.58 U44.2 U44.3 | length 1072.9
  Component Side w10: U1.58@13907.11,6666.27 v3@14299.36,6666.27 ; v1(14551.88,6209.52) U44.3@14621.88,6209.52 ; U44.3@14621.88,6205.31 U44.3@14621.88,6209.52 ; U44.2@14621.88,6255.7 U44.3@14621.88,6209.52
  Solder Side w10: v3@14299.69,6666.27 14299.69,6457.5 v1@14547.67,6209.52 ; v1(14551.88,6209.52) v1@14551.88,6210.31
  other v3: 14298.69,6666.14
RS485_RE2: U1.39 U45.2 U45.3 | length 1056.4
  Component Side w10: U1.39@13659.08,6418.24 13659.08,5758.11 13702.67,5714.52 U45.3@13986.88,5714.52 U45.2@13986.88,5764.91
SENSE_H: R14.1 SENSE_H.1 | length 978
  Component Side w30: SENSE_H.1@7283.57,8120.58 7283.57,7883.49 7505.77,7661.29 7750.11,7661.29 ; 7749.6,7661.27 R14.1@7931.92,7661.27
SENSE_L: R12.1 SENSE_L.1 | length 1548.2
  Component Side w30: SENSE_L.1@7295.36,6937.6 v2@7709.54,6937.6 ; v2@7716.52,7852.88 R12.1@7936.93,7852.88
  Solder Side w30: v2(7715.75,6933.67) v2@7715.75,7847.31
  other v2: 7715.74,7853.66
SIGIN: C48.1 SigIn.1 U3.3 U14.3 | length 1842.5
  Component Side w10: U3.3@11638.09,9032.65 U3.3@11638.83,9033.38 ; C48.1@11902.91,7805.92 11934.09,7837.1 U14.3@11987.2,7837.1
  Component Side w20: SigIn.1@11455.69,7760.35 11878.34,7760.35 11899.28,7781.29 C48.1@11899.28,7806.33 ; v3@11636.52,8734.96 U3.3@11636.52,9026.94
  Solder Side w20: v3@11635.71,7760.12 v3(11635.71,8735.12)
  other v3: 11639.42,7760.89
SWCLK: DL.2 U1.49 | length 4290.2
  Component Side w10: U1.49@13907.11,6489.11 14399.1,6489.11 14545.62,6635.63 14545.62,9127.18 14688.75,9270.31 DL.2@15575.29,9270.31 ; DL.2@15565.53,9270.19 DL.2@15576,9270.19
SWDIO: DL.3 DL.4 U1.46 | length 4998.8
  Component Side w10: U1.46@13796.88,6418.24 13796.88,6236.03 13847.6,6185.31 14286.88,6185.31 14581.88,6480.31 14581.88,9050.31 14691.88,9160.31 15615.05,9160.31 15641,9186.26 15641,9282.76 15627.98,9295.78 15565.53,9295.78 DL.4@15565.53,9321.37
UART3_RX: LCD.5 U1.30 | length 3147.3
  Component Side w10: v1@13063.94,6463.87 13132.9,6463.87 13197.5,6528.48 U1.30@13470.11,6528.48
  Solder Side w10: v1@13063.78,6460.29 13063.78,8886.65 13063.51,8886.93 LCD.5@13266.88,9090.31
  other v1: 13064.82,6462.05
UART3_TX: LCD.3 LCD.4 U1.29 | length 2919.2
  Component Side w10: v1@13113.3,6512.03 13142.34,6512.03 13178.47,6548.16 U1.29@13470.11,6548.16
  Solder Side w10: v1@13109.67,6511.3 13109.67,8732.9 LCD.3@13269.37,8892.61 ; LCD.3@13266.88,8890.31 LCD.4@13266.88,8990.31
  other v1: 13111.49,6511.41
USART1_RX: U1.43 U44.1 | length 1262.7
  Component Side w10: U1.43@13737.82,6418.24 13737.82,6159.37 13806.88,6090.31 14321.88,6090.31 14541.88,6310.31 U44.1@14621.88,6310.31
USART1_TX: U1.42 U44.4 | length 1257
  Component Side w10: U1.42@13718.14,6418.24 13718.14,6139.06 13796.88,6060.31 14336.88,6060.31 14436.88,6160.31 U44.4@14621.88,6160.31
USART2_RX: U1.17 U45.1 | length 2908.4
  Component Side w10: v1@12768.67,6863.92 13344.23,6863.92 13423.77,6784.38 U1.17@13470.11,6784.38 ; v1@13710.87,5815.31 U45.1@13986.88,5815.31
  Solder Side w10: v1(12762.28,6862.93) 12762.28,5976.07 12762.58,5975.77 12761.16,5974.34 12920.44,5815.06 v1@13703.87,5815.06
  other v1: 13705.53,5814.43
USART2_TX: U1.16 U45.4 | length 3167
  Component Side w10: v1@12710.15,6892.48 13371.02,6892.48 13408.25,6855.25 U1.16@13540.97,6855.25 ; v1@13701.63,5664.13 U45.4@13986.88,5664.13
  Solder Side w10: v1(12716.44,6892.2) 12716.44,5954.87 12717.3,5955.72 13010.18,5662.84 v1@13692.98,5662.84
  other v1: 13698.23,5662.68
USB_DM: R43.2 U1.44 | length 3171.6
  Component Side w10: U1.44@13757.51,6418.24 13757.51,6179.69 13816.88,6120.31 14311.88,6120.31 14661.88,6470.31 14661.88,8165.31 14730.28,8233.71 R43.2@14797.67,8233.71
USB_DP: R41.2 R42.2 U1.45 | length 3169.1
  Component Side w10: U1.45@13777.19,6418.24 13777.19,6205 13831.88,6150.31 14296.88,6150.31 14626.88,6480.31 14626.88,8214.27 R42.2@14727.9,8315.29 ; R42.2@14726.88,8315.31 R41.2@14796.88,8315.31
pads on no net: DL.1 J1.1 J1.4 J1.5 J1.6 J1.7 J1.8 J1.9 J1.10 J1.11 K1.2 K1.7 K2.2 K2.7 K3.2 K3.7 K4.2 K4.7 K5.2 K5.7 K6.2 K6.7 K7.2 K7.7 K8.2 K8.7 K9.2 K9.7 K10.2 K10.7 K11.3 K11.6 K12.4 K13.1 K13.4 K14.1 K14.4 LCD.6 U1.2 U1.3 U1.4 U1.7 U1.34 U1.50 U1.57 U1.59 U1.61 U1.62 U9.1 U9.5 U9.6 U12.1 U12.3 U12.5 U12.7 U12.8 U14.2 U14.6 U14.8 U17.7 U18.7 USB.1
copper on no net:
  other v4: 15606,9200.31 15606,9391.25
  other v5: 15711.51,9153.06 15711.51,9438.5

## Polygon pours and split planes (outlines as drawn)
DGND on Solder Side "S_DGND" (solid, remove dead copper, pour order 6): 15749.94,9644.36 15749.92,9644.38 12831.45,9644.38 12831.4,9644.38 12362.6,9175.58 12362.3,9175.28 12362.3,4860.6 15768.97,4860.6 15769.25,4860.32
AGND on Solder Side "S_AGND" (solid, remove dead copper, pour order 8): 7108.29,12278.29 7108.97,12278.97 15768.48,12278.97 15768.48,9674.5 15768.83,9674.16 15768.76,9674.22 12819.85,9674.22 12819.04,9674.22 12332.06,9187.24 12332.9,9186.4 12332.9,4841.06 7109.06,4841.06 7108.83,4841.29
DGND on Component Side "T_DGND" (solid, remove dead copper, pour order 4): 15749.77,9643.76 15749.16,9644.37 12831.67,9644.37 12831.45,9644.37 12362.7,9175.62 12362.63,9175.55 12362.63,4860.7 15750.09,4860.7 15751.3,4859.49
AGND on Component Side "T_AGND" (solid, remove dead copper, pour order 10): 7108.81,12278.63 7109.11,12278.33 15769.11,12278.33 15769.11,9674.32 15768.93,9674.14 15768.84,9674.23 12819.06,9674.23 12819.04,9674.23 12332.83,9188.02 12332.82,9188 12332.82,4840.73 7109.27,4840.73 7109.23,4840.77
DGND on Ground Plane (split plane): 15749.96,4947.73 15663.31,4861.08 12362.7,4861.08 12362.7,9175.54 12831.17,9644.02 15749.96,9644.02
AGND on Ground Plane (split plane): 15749.96,12171.24 15749.96,9674.16 12822.63,9674.16 12819.69,9673.87 12816.86,9673.02 12814.25,9671.62 12811.97,9669.75 12810.09,9667.46 12808.7,9664.86 12808.41,9663.88 12342.84,9198.31 12341.86,9198.02 12339.25,9196.62 12336.97,9194.75 12335.09,9192.46 12333.7,9189.86 12332.84,9187.03 12332.55,9184.09 12332.55,4861.08 7128.74,4861.08 7128.74,12257.89 15663.31,12257.89
D3V3 on Power Plane (split plane): 15749.96,4947.73 15663.31,4861.08 12357.7,4861.08 12357.7,9168.4 12358.41,9168.98 12828.45,9639.02 15749.96,9639.02
AGND on Power Plane (split plane): 15749.96,12171.24 15749.96,9669.16 12826.55,9669.16 12825.69,9669.42 12822.75,9669.71 12819.81,9669.42 12818.96,9669.16 12817.63,9669.16 12814.69,9668.87 12811.86,9668.02 12809.25,9666.62 12806.97,9664.75 12805.09,9662.46 12803.7,9659.86 12802.84,9657.03 12802.74,9655.94 12340.78,9193.98 12339.69,9193.87 12336.86,9193.02 12334.25,9191.62 12331.97,9189.75 12330.09,9187.46 12328.7,9184.86 12327.84,9182.03 12327.55,9179.09 12327.55,4861.08 7128.74,4861.08 7128.74,12257.89 15663.31,12257.89

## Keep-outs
Keep-Out Layer:
  circle w10: c15662.11,12059.17 r53.15
  circle w10: c7249.91,12059.17 r53.15
  circle w10: c7249.91,5059.17 r53.15
  circle w10: c15662.11,5059.17 r53.15
  lines w10: 7108.64,4840.98 15671.64,4840.98 15770.06,4939.41 15770.06,12179.56 15671.64,12277.99 7108.64,12277.99 ; 7109.36,4840.67 7109.36,12277.67 15672.35,12277.67 15770.77,12179.25 15770.77,4939.09 15672.35,4840.67 7109.36,4840.67

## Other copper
Component Side:
  rectangle net DGND: 13231.88,8660.31 13471.88,8820.31
  rectangle net DGND: 13749.93,8724.48 13812.45,8734.68
  rectangle net D3V3: 13936.88,8795.31 14131.88,8960.31
  rectangle net DGND: 13749.93,8734.68 13812.45,8781.97
  pour cut-out: 7109.26,5210.29 7109.26,4840.74 7399.26,4840.74 7399.26,5210.29
  pour cut-out: 7108.13,12278.06 7108.13,11908.51 7398.13,11908.51 7398.13,12278.06
  pour cut-out: 15481.13,12278.36 15481.13,11908.82 15771.13,11908.82 15771.13,12278.36
  pour cut-out: 15478.67,5210.53 15478.67,4840.98 15768.67,4840.98 15768.67,5210.53
Ground Plane (plane layer: these items are gaps in the copper):
  lines w30: 12347.63,4839.33 12347.63,9184.09 ; 12349.72,9183.88 12824.72,9658.88 ; 12822.63,9659.09 15774.48,9659.09
Power Plane (plane layer: these items are gaps in the copper):
  lines w30: 12342.63,4847.86 12342.63,9179.09 ; 12347.75,9179.64 12822.75,9654.64 ; 12817.63,9654.09 15765.07,9654.09

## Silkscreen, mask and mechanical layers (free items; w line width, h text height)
Top Overlay:
  drawing of 4936 lines, arcs and shapes, not listed
  text "+" at 7169.89,11253.52 h60
  text "+" at 7167.27,10783.24 h60
  text "SMU_V2.0_20180207" at 13407.77,9794.2 h100
  text "+" at 13148.92,9372.62 h60
  text "-" at 13149.8,8667.44 h60
Mechanical 1:
  circle w10: c15662.11,12059.17 r53.15
  circle w10: c7249.91,12059.17 r53.15
  circle w10: c7249.91,5059.17 r53.15
  circle w10: c15662.11,5059.17 r53.15
  lines w10: 7109.36,4840.67 15672.35,4840.67 15770.77,4939.09 15770.77,12179.25 15672.35,12277.67 7109.36,12277.67 7109.36,4840.67

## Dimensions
7102.28,4635.66 to 15764.65,4593.54 on Top Overlay
15908.52,4838.09 to 16089.02,12280.74 on Top Overlay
